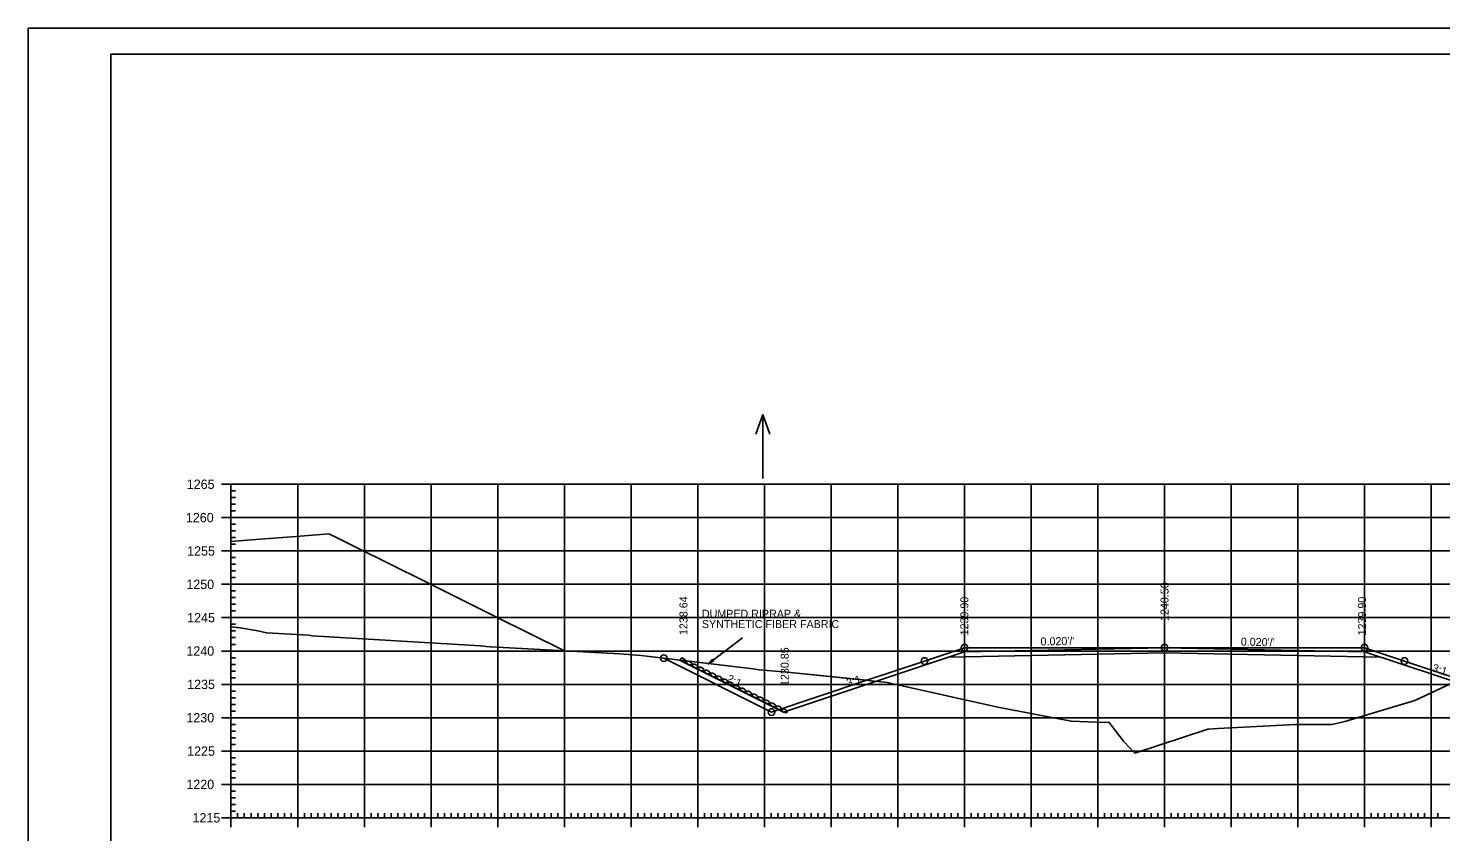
# Model space of a CAD drawing. Extents: x 1406028 to 1412453, y 321733 to 325986.
# Drawn here: x 1410609.2 to 1410821, y 322356.3 to 322476.8 of the extents above; entities that cross this region are included whole.
import ezdxf

# ---------------------------------------------------------------- set-up
doc = ezdxf.new("R2010")
doc.units = 0
for name, color, linetype in [('R_Alt Surface', 7, 'Continuous'), ('R_Axis', 7, 'Continuous'), ('R_Axis Annot', 7, 'Continuous'), ('R_Border', 7, 'Continuous'), ('R_Draft', 7, 'Continuous'), ('R_Exist Surface', 7, 'Continuous'), ('R_Fin Surface', 7, 'Continuous'), ('R_Fin Surface Annot', 7, 'Continuous'), ('R_Grid', 7, 'Continuous'), ('R_No Plot', 7, 'Continuous'), ('R_Water Annot', 7, 'Continuous')]:
    doc.layers.add(name, color=color, linetype=linetype)

msp = doc.modelspace()

# ---------------------------------------------------------------- linework, layer by layer
at = {"layer": 'R_Alt Surface'}
msp.add_lwpolyline([(1410747.2, 322382.53), (1410779.59, 322383.18), (1410811.99, 322382.53)], dxfattribs=at)
at = {"layer": 'R_Axis'}
for p, q in [((1410638.19, 322408.43), (1410640.99, 322408.43)), ((1410639.59, 322358.43), (1410639.59, 322408.43)), ((1410639.59, 322407.43), (1410640.29, 322407.43)), ((1410639.59, 322406.43), (1410640.29, 322406.43)), ((1410639.59, 322405.43), (1410640.29, 322405.43)), ((1410638.19, 322403.43), (1410640.99, 322403.43)), ((1410639.59, 322404.43), (1410640.29, 322404.43)), ((1410639.59, 322402.43), (1410640.29, 322402.43)), ((1410639.59, 322401.43), (1410640.29, 322401.43)), ((1410639.59, 322400.43), (1410640.29, 322400.43)), ((1410639.59, 322399.43), (1410640.29, 322399.43)), ((1410638.19, 322398.43), (1410640.99, 322398.43)), ((1410639.59, 322397.43), (1410640.29, 322397.43)), ((1410639.59, 322396.43), (1410640.29, 322396.43)), ((1410639.59, 322395.43), (1410640.29, 322395.43)), ((1410638.19, 322393.43), (1410640.99, 322393.43)), ((1410639.59, 322394.43), (1410640.29, 322394.43)), ((1410639.59, 322392.43), (1410640.29, 322392.43)), ((1410639.59, 322391.43), (1410640.29, 322391.43)), ((1410639.59, 322390.43), (1410640.29, 322390.43)), ((1410638.19, 322388.43), (1410640.99, 322388.43)), ((1410639.59, 322389.43), (1410640.29, 322389.43)), ((1410639.59, 322387.43), (1410640.29, 322387.43)), ((1410639.59, 322386.43), (1410640.29, 322386.43)), ((1410639.59, 322385.43), (1410640.29, 322385.43)), ((1410639.59, 322384.43), (1410640.29, 322384.43)), ((1410638.19, 322383.43), (1410640.99, 322383.43)), ((1410639.59, 322382.43), (1410640.29, 322382.43)), ((1410639.59, 322381.43), (1410640.29, 322381.43)), ((1410639.59, 322380.43), (1410640.29, 322380.43)), ((1410638.19, 322378.43), (1410640.99, 322378.43)), ((1410639.59, 322379.43), (1410640.29, 322379.43)), ((1410639.59, 322377.43), (1410640.29, 322377.43)), ((1410639.59, 322376.43), (1410640.29, 322376.43)), ((1410639.59, 322375.43), (1410640.29, 322375.43)), ((1410639.59, 322374.43), (1410640.29, 322374.43)), ((1410638.19, 322373.43), (1410640.99, 322373.43)), ((1410639.59, 322372.43), (1410640.29, 322372.43)), ((1410639.59, 322371.43), (1410640.29, 322371.43)), ((1410639.59, 322370.43), (1410640.29, 322370.43)), ((1410639.59, 322369.43), (1410640.29, 322369.43)), ((1410638.19, 322368.43), (1410640.99, 322368.43)), ((1410639.59, 322367.43), (1410640.29, 322367.43)), ((1410639.59, 322366.43), (1410640.29, 322366.43)), ((1410639.59, 322365.43), (1410640.29, 322365.43)), ((1410638.19, 322363.43), (1410640.99, 322363.43)), ((1410639.59, 322364.43), (1410640.29, 322364.43)), ((1410639.59, 322362.43), (1410640.29, 322362.43)), ((1410639.59, 322361.43), (1410640.29, 322361.43)), ((1410639.59, 322360.43), (1410640.29, 322360.43)), ((1410639.59, 322357.03), (1410639.59, 322359.83)), ((1410639.59, 322359.43), (1410640.29, 322359.43)), ((1410640.59, 322358.43), (1410640.59, 322359.13)), ((1410641.59, 322358.43), (1410641.59, 322359.13)), ((1410642.59, 322358.43), (1410642.59, 322359.13)), ((1410643.59, 322358.43), (1410643.59, 322359.13)), ((1410644.59, 322358.43), (1410644.59, 322359.13)), ((1410645.59, 322358.43), (1410645.59, 322359.13)), ((1410646.59, 322358.43), (1410646.59, 322359.13)), ((1410647.59, 322358.43), (1410647.59, 322359.13)), ((1410648.59, 322358.43), (1410648.59, 322359.13)), ((1410649.59, 322357.03), (1410649.59, 322359.83)), ((1410650.59, 322358.43), (1410650.59, 322359.13)), ((1410651.59, 322358.43), (1410651.59, 322359.13)), ((1410652.59, 322358.43), (1410652.59, 322359.13)), ((1410653.59, 322358.43), (1410653.59, 322359.13)), ((1410654.59, 322358.43), (1410654.59, 322359.13)), ((1410655.59, 322358.43), (1410655.59, 322359.13)), ((1410656.59, 322358.43), (1410656.59, 322359.13)), ((1410657.59, 322358.43), (1410657.59, 322359.13)), ((1410658.59, 322358.43), (1410658.59, 322359.13)), ((1410659.59, 322357.03), (1410659.59, 322359.83)), ((1410660.59, 322358.43), (1410660.59, 322359.13)), ((1410661.59, 322358.43), (1410661.59, 322359.13)), ((1410662.59, 322358.43), (1410662.59, 322359.13)), ((1410663.59, 322358.43), (1410663.59, 322359.13)), ((1410664.59, 322358.43), (1410664.59, 322359.13)), ((1410665.59, 322358.43), (1410665.59, 322359.13)), ((1410666.59, 322358.43), (1410666.59, 322359.13)), ((1410667.59, 322358.43), (1410667.59, 322359.13)), ((1410668.59, 322358.43), (1410668.59, 322359.13)), ((1410669.59, 322357.03), (1410669.59, 322359.83)), ((1410670.59, 322358.43), (1410670.59, 322359.13)), ((1410671.59, 322358.43), (1410671.59, 322359.13)), ((1410672.59, 322358.43), (1410672.59, 322359.13)), ((1410673.59, 322358.43), (1410673.59, 322359.13)), ((1410674.59, 322358.43), (1410674.59, 322359.13)), ((1410675.59, 322358.43), (1410675.59, 322359.13)), ((1410676.59, 322358.43), (1410676.59, 322359.13)), ((1410677.59, 322358.43), (1410677.59, 322359.13)), ((1410678.59, 322358.43), (1410678.59, 322359.13)), ((1410679.59, 322357.03), (1410679.59, 322359.83)), ((1410680.59, 322358.43), (1410680.59, 322359.13)), ((1410681.59, 322358.43), (1410681.59, 322359.13)), ((1410682.59, 322358.43), (1410682.59, 322359.13)), ((1410683.59, 322358.43), (1410683.59, 322359.13)), ((1410684.59, 322358.43), (1410684.59, 322359.13)), ((1410685.59, 322358.43), (1410685.59, 322359.13)), ((1410686.59, 322358.43), (1410686.59, 322359.13)), ((1410687.59, 322358.43), (1410687.59, 322359.13)), ((1410688.59, 322358.43), (1410688.59, 322359.13)), ((1410689.59, 322357.03), (1410689.59, 322359.83)), ((1410690.59, 322358.43), (1410690.59, 322359.13)), ((1410691.59, 322358.43), (1410691.59, 322359.13)), ((1410692.59, 322358.43), (1410692.59, 322359.13)), ((1410693.59, 322358.43), (1410693.59, 322359.13)), ((1410694.59, 322358.43), (1410694.59, 322359.13)), ((1410695.59, 322358.43), (1410695.59, 322359.13)), ((1410696.59, 322358.43), (1410696.59, 322359.13)), ((1410697.59, 322358.43), (1410697.59, 322359.13)), ((1410698.59, 322358.43), (1410698.59, 322359.13)), ((1410699.59, 322357.03), (1410699.59, 322359.83)), ((1410700.59, 322358.43), (1410700.59, 322359.13)), ((1410701.59, 322358.43), (1410701.59, 322359.13)), ((1410702.59, 322358.43), (1410702.59, 322359.13)), ((1410703.59, 322358.43), (1410703.59, 322359.13)), ((1410704.59, 322358.43), (1410704.59, 322359.13)), ((1410705.59, 322358.43), (1410705.59, 322359.13)), ((1410706.59, 322358.43), (1410706.59, 322359.13)), ((1410707.59, 322358.43), (1410707.59, 322359.13)), ((1410708.59, 322358.43), (1410708.59, 322359.13)), ((1410709.59, 322357.03), (1410709.59, 322359.83)), ((1410710.59, 322358.43), (1410710.59, 322359.13)), ((1410711.59, 322358.43), (1410711.59, 322359.13)), ((1410712.59, 322358.43), (1410712.59, 322359.13)), ((1410713.59, 322358.43), (1410713.59, 322359.13)), ((1410714.59, 322358.43), (1410714.59, 322359.13)), ((1410715.59, 322358.43), (1410715.59, 322359.13)), ((1410716.59, 322358.43), (1410716.59, 322359.13)), ((1410717.59, 322358.43), (1410717.59, 322359.13)), ((1410718.59, 322358.43), (1410718.59, 322359.13)), ((1410719.59, 322357.03), (1410719.59, 322359.83)), ((1410720.59, 322358.43), (1410720.59, 322359.13)), ((1410721.59, 322358.43), (1410721.59, 322359.13)), ((1410722.59, 322358.43), (1410722.59, 322359.13)), ((1410723.59, 322358.43), (1410723.59, 322359.13)), ((1410724.59, 322358.43), (1410724.59, 322359.13)), ((1410725.59, 322358.43), (1410725.59, 322359.13)), ((1410726.59, 322358.43), (1410726.59, 322359.13)), ((1410727.59, 322358.43), (1410727.59, 322359.13)), ((1410728.59, 322358.43), (1410728.59, 322359.13)), ((1410729.59, 322357.03), (1410729.59, 322359.83)), ((1410730.59, 322358.43), (1410730.59, 322359.13)), ((1410731.59, 322358.43), (1410731.59, 322359.13)), ((1410732.59, 322358.43), (1410732.59, 322359.13)), ((1410733.59, 322358.43), (1410733.59, 322359.13)), ((1410734.59, 322358.43), (1410734.59, 322359.13)), ((1410735.59, 322358.43), (1410735.59, 322359.13)), ((1410736.59, 322358.43), (1410736.59, 322359.13)), ((1410737.59, 322358.43), (1410737.59, 322359.13)), ((1410738.59, 322358.43), (1410738.59, 322359.13)), ((1410739.59, 322357.03), (1410739.59, 322359.83)), ((1410740.59, 322358.43), (1410740.59, 322359.13)), ((1410741.59, 322358.43), (1410741.59, 322359.13)), ((1410742.59, 322358.43), (1410742.59, 322359.13)), ((1410743.59, 322358.43), (1410743.59, 322359.13)), ((1410744.59, 322358.43), (1410744.59, 322359.13)), ((1410745.59, 322358.43), (1410745.59, 322359.13)), ((1410746.59, 322358.43), (1410746.59, 322359.13)), ((1410747.59, 322358.43), (1410747.59, 322359.13)), ((1410748.59, 322358.43), (1410748.59, 322359.13)), ((1410749.59, 322357.03), (1410749.59, 322359.83)), ((1410750.59, 322358.43), (1410750.59, 322359.13)), ((1410751.59, 322358.43), (1410751.59, 322359.13)), ((1410752.59, 322358.43), (1410752.59, 322359.13)), ((1410753.59, 322358.43), (1410753.59, 322359.13)), ((1410754.59, 322358.43), (1410754.59, 322359.13)), ((1410755.59, 322358.43), (1410755.59, 322359.13)), ((1410756.59, 322358.43), (1410756.59, 322359.13)), ((1410757.59, 322358.43), (1410757.59, 322359.13)), ((1410758.59, 322358.43), (1410758.59, 322359.13)), ((1410759.59, 322357.03), (1410759.59, 322359.83)), ((1410760.59, 322358.43), (1410760.59, 322359.13)), ((1410761.59, 322358.43), (1410761.59, 322359.13)), ((1410762.59, 322358.43), (1410762.59, 322359.13)), ((1410763.59, 322358.43), (1410763.59, 322359.13)), ((1410764.59, 322358.43), (1410764.59, 322359.13)), ((1410765.59, 322358.43), (1410765.59, 322359.13)), ((1410766.59, 322358.43), (1410766.59, 322359.13)), ((1410767.59, 322358.43), (1410767.59, 322359.13)), ((1410768.59, 322358.43), (1410768.59, 322359.13)), ((1410769.59, 322357.03), (1410769.59, 322359.83)), ((1410770.59, 322358.43), (1410770.59, 322359.13)), ((1410771.59, 322358.43), (1410771.59, 322359.13)), ((1410772.59, 322358.43), (1410772.59, 322359.13)), ((1410773.59, 322358.43), (1410773.59, 322359.13)), ((1410774.59, 322358.43), (1410774.59, 322359.13)), ((1410775.59, 322358.43), (1410775.59, 322359.13)), ((1410776.59, 322358.43), (1410776.59, 322359.13)), ((1410777.59, 322358.43), (1410777.59, 322359.13)), ((1410778.59, 322358.43), (1410778.59, 322359.13)), ((1410779.59, 322357.03), (1410779.59, 322359.83)), ((1410780.59, 322358.43), (1410780.59, 322359.13)), ((1410781.59, 322358.43), (1410781.59, 322359.13)), ((1410782.59, 322358.43), (1410782.59, 322359.13)), ((1410783.59, 322358.43), (1410783.59, 322359.13)), ((1410784.59, 322358.43), (1410784.59, 322359.13)), ((1410785.59, 322358.43), (1410785.59, 322359.13)), ((1410786.59, 322358.43), (1410786.59, 322359.13)), ((1410787.59, 322358.43), (1410787.59, 322359.13)), ((1410788.59, 322358.43), (1410788.59, 322359.13)), ((1410789.59, 322357.03), (1410789.59, 322359.83)), ((1410790.59, 322358.43), (1410790.59, 322359.13)), ((1410791.59, 322358.43), (1410791.59, 322359.13)), ((1410792.59, 322358.43), (1410792.59, 322359.13)), ((1410793.59, 322358.43), (1410793.59, 322359.13)), ((1410794.59, 322358.43), (1410794.59, 322359.13)), ((1410795.59, 322358.43), (1410795.59, 322359.13)), ((1410796.59, 322358.43), (1410796.59, 322359.13)), ((1410797.59, 322358.43), (1410797.59, 322359.13)), ((1410798.59, 322358.43), (1410798.59, 322359.13)), ((1410799.59, 322357.03), (1410799.59, 322359.83)), ((1410800.59, 322358.43), (1410800.59, 322359.13)), ((1410801.59, 322358.43), (1410801.59, 322359.13)), ((1410802.59, 322358.43), (1410802.59, 322359.13)), ((1410803.59, 322358.43), (1410803.59, 322359.13)), ((1410804.59, 322358.43), (1410804.59, 322359.13)), ((1410805.59, 322358.43), (1410805.59, 322359.13)), ((1410806.59, 322358.43), (1410806.59, 322359.13)), ((1410807.59, 322358.43), (1410807.59, 322359.13)), ((1410808.59, 322358.43), (1410808.59, 322359.13)), ((1410809.59, 322357.03), (1410809.59, 322359.83)), ((1410810.59, 322358.43), (1410810.59, 322359.13)), ((1410811.59, 322358.43), (1410811.59, 322359.13)), ((1410812.59, 322358.43), (1410812.59, 322359.13)), ((1410813.59, 322358.43), (1410813.59, 322359.13)), ((1410814.59, 322358.43), (1410814.59, 322359.13)), ((1410815.59, 322358.43), (1410815.59, 322359.13)), ((1410816.59, 322358.43), (1410816.59, 322359.13)), ((1410817.59, 322358.43), (1410817.59, 322359.13)), ((1410818.59, 322358.43), (1410818.59, 322359.13)), ((1410819.59, 322357.03), (1410819.59, 322359.83)), ((1410820.59, 322358.43), (1410820.59, 322359.13)), ((1410638.19, 322358.43), (1410640.99, 322358.43)), ((1410639.59, 322358.43), (1410919.59, 322358.43))]:
    msp.add_line(p, q, dxfattribs=at)
at = {"layer": 'R_Border'}
for p, q in [((1410621.59, 322472.89), (1410937.77, 322472.89)), ((1410621.59, 322267.43), (1410621.59, 322472.89)), ((1410774.11, 322472.63), (1410774.11, 322472.63)), ((1410774.11, 322472.63), (1410774.11, 322472.63))]:
    msp.add_line(p, q, dxfattribs=at)
at = {"layer": 'R_Draft'}
for p, q in [((1410716.31, 322385.39), (1410711.08, 322381.47)), ((1410711.79, 322382.19), (1410711.08, 322381.47)), ((1410711.8, 322382.17), (1410711.21, 322381.57)), ((1410711.95, 322381.97), (1410711.21, 322381.57)), ((1410711.82, 322382.14), (1410711.35, 322381.67)), ((1410711.94, 322381.99), (1410711.35, 322381.67)), ((1410711.83, 322382.12), (1410711.48, 322381.77)), ((1410711.92, 322382.01), (1410711.48, 322381.77)), ((1410711.85, 322382.1), (1410711.62, 322381.87)), ((1410711.91, 322382.03), (1410711.62, 322381.87)), ((1410711.86, 322382.08), (1410711.75, 322381.97)), ((1410711.89, 322382.05), (1410711.75, 322381.97)), ((1410711.79, 322382.19), (1410711.97, 322381.95)), ((1410711.97, 322381.95), (1410711.08, 322381.47))]:
    msp.add_line(p, q, dxfattribs=at)
for centre in [(1410707.42, 322382.07), (1410708.31, 322381.62), (1410709.21, 322381.17), (1410710.1, 322380.73), (1410711, 322380.28), (1410711.89, 322379.83), (1410712.78, 322379.39), (1410713.68, 322378.94), (1410714.57, 322378.49), (1410715.47, 322378.04), (1410716.36, 322377.6), (1410717.26, 322377.15), (1410718.15, 322376.7), (1410719.05, 322376.26), (1410719.94, 322375.81), (1410720.83, 322375.36), (1410721.73, 322374.91), (1410722.62, 322374.47)]:
    msp.add_ellipse(centre, major_axis=(0.389, -0.201), ratio=0.517889, dxfattribs=at)
at = {"layer": 'R_Exist Surface'}
msp.add_lwpolyline([(1410639.59, 322387.04), (1410640.97, 322386.89), (1410643.63, 322386.43), (1410644.91, 322386.15), (1410651.23, 322385.78), (1410651.78, 322385.7), (1410676.99, 322384.22), (1410677.87, 322384.13), (1410678.46, 322384.08), (1410679.51, 322384.02), (1410697.89, 322382.99), (1410701.09, 322382.75), (1410717.91, 322380.75), (1410718.8, 322380.63), (1410722.99, 322380.25), (1410735.65, 322378.97), (1410738.02, 322378.69), (1410754.61, 322375.03), (1410765.59, 322372.93), (1410770.6, 322372.71), (1410771.24, 322372.78), (1410773.43, 322369.89), (1410775.12, 322368.14), (1410785.79, 322371.59), (1410786.07, 322371.7), (1410786.09, 322371.7), (1410786.18, 322371.72), (1410787.58, 322371.79), (1410799.23, 322372.41), (1410804.73, 322372.39), (1410806.61, 322372.84), (1410817.15, 322376.03), (1410824.38, 322379.42)], dxfattribs=at)
at = {"layer": 'R_Fin Surface'}
for p, q in [((1410722.44, 322374.28), (1410706.87, 322382.06)), ((1410749.59, 322383.33), (1410722.44, 322374.28)), ((1410809.59, 322383.33), (1410830.78, 322376.26))]:
    msp.add_line(p, q, dxfattribs=at)
for points in [[(1410639.59, 322399.84), (1410642.68, 322400.09), (1410649.34, 322400.62), (1410654.24, 322401.01), (1410655.51, 322400.38), (1410658.73, 322398.78), (1410662.74, 322396.79), (1410669.41, 322393.48), (1410679.3, 322388.57), (1410689.6, 322383.46)], [(1410749.59, 322383.33), (1410779.59, 322383.93), (1410809.59, 322383.33)]]:
    msp.add_lwpolyline(points, dxfattribs=at)
at = {"layer": 'R_Grid'}
for p, q in [((1410639.59, 322408.43), (1410919.59, 322408.43)), ((1410639.59, 322358.43), (1410639.59, 322408.43)), ((1410649.59, 322358.43), (1410649.59, 322408.43)), ((1410659.59, 322358.43), (1410659.59, 322408.43)), ((1410669.59, 322358.43), (1410669.59, 322408.43)), ((1410679.59, 322358.43), (1410679.59, 322408.43)), ((1410689.59, 322358.43), (1410689.59, 322408.43)), ((1410699.59, 322358.43), (1410699.59, 322408.43)), ((1410709.59, 322358.43), (1410709.59, 322408.43)), ((1410719.59, 322358.43), (1410719.59, 322408.43)), ((1410729.59, 322358.43), (1410729.59, 322408.43)), ((1410739.59, 322358.43), (1410739.59, 322408.43)), ((1410749.59, 322358.43), (1410749.59, 322408.43)), ((1410759.59, 322358.43), (1410759.59, 322408.43)), ((1410769.59, 322358.43), (1410769.59, 322408.43)), ((1410779.59, 322358.43), (1410779.59, 322408.43)), ((1410789.59, 322358.43), (1410789.59, 322408.43)), ((1410799.59, 322358.43), (1410799.59, 322408.43)), ((1410809.59, 322358.43), (1410809.59, 322408.43)), ((1410819.59, 322358.43), (1410819.59, 322408.43)), ((1410639.59, 322403.43), (1410919.59, 322403.43)), ((1410639.59, 322398.43), (1410919.59, 322398.43)), ((1410639.59, 322393.43), (1410919.59, 322393.43)), ((1410639.59, 322388.43), (1410919.59, 322388.43)), ((1410639.59, 322383.43), (1410919.59, 322383.43)), ((1410639.59, 322378.43), (1410919.59, 322378.43)), ((1410639.59, 322373.43), (1410919.59, 322373.43)), ((1410639.59, 322368.43), (1410919.59, 322368.43)), ((1410639.59, 322363.43), (1410919.59, 322363.43)), ((1410639.59, 322358.43), (1410919.59, 322358.43))]:
    msp.add_line(p, q, dxfattribs=at)
at = {"layer": 'R_No Plot'}
msp.add_line((1410609.19, 322476.78), (1410942.52, 322476.78), dxfattribs=at)
for points in [[(1410609.18, 322476.78), (1410942.52, 322476.78), (1410942.52, 322263.44), (1410609.18, 322263.44)], [(1410855.51, 322472.89), (1410875.13, 322472.89), (1410875.13, 322463.01), (1410891.24, 322463.01), (1410914.44, 322463.01), (1410914.44, 322438.67), (1410937.77, 322438.67), (1410937.77, 322267.43), (1410621.59, 322267.43), (1410621.59, 322472.89)], [(1410704.51, 322382.35), (1410717.91, 322380.75), (1410718.8, 322380.63), (1410722.99, 322380.25), (1410734.93, 322379.04), (1410720.64, 322374.28)], [(1410734.93, 322379.04), (1410735.65, 322378.97), (1410738.02, 322378.69), (1410754.61, 322375.03), (1410765.59, 322372.93), (1410770.6, 322372.71), (1410771.24, 322372.78), (1410773.43, 322369.89), (1410775.12, 322368.14), (1410785.79, 322371.59), (1410786.07, 322371.7), (1410786.09, 322371.7), (1410786.18, 322371.72), (1410787.58, 322371.79), (1410799.23, 322372.41), (1410804.73, 322372.39), (1410806.61, 322372.84), (1410817.15, 322376.03), (1410823.86, 322379.17), (1410815.59, 322381.93), (1410809.59, 322383.93), (1410779.59, 322383.93), (1410749.59, 322383.93), (1410743.59, 322381.93)]]:
    msp.add_lwpolyline(points, close=True, dxfattribs=at)
for centre in [(1410749.59, 322383.93), (1410749.59, 322383.93), (1410779.59, 322383.93), (1410809.59, 322383.93), (1410809.59, 322383.93), (1410704.51, 322382.35), (1410743.59, 322381.93), (1410815.59, 322381.93), (1410720.64, 322374.28), (1410720.64, 322374.28)]:
    msp.add_circle(centre, 0.5, dxfattribs=at)
at = {"layer": 'R_Water Annot'}
for p, q in [((1410719.35, 322418.86), (1410718.28, 322415.93)), ((1410719.35, 322409.28), (1410719.35, 322418.86)), ((1410719.35, 322418.86), (1410720.42, 322415.93))]:
    msp.add_line(p, q, dxfattribs=at)

# ---------------------------------------------------------------- texts
at = {"layer": 'R_Axis Annot'}
for s, p in [('1265', (1410632.96, 322407.73)), ('1260', (1410632.83, 322402.73)), ('1255', (1410633.02, 322397.73)), ('1250', (1410632.9, 322392.73)), ('1245', (1410633.02, 322387.73)), ('1240', (1410632.9, 322382.73)), ('1235', (1410633.02, 322377.73)), ('1230', (1410632.9, 322372.73)), ('1225', (1410633.02, 322367.73)), ('1220', (1410632.9, 322362.73)), ('1215', (1410633.82, 322357.73))]:
    msp.add_text(s, height=1.4, dxfattribs=at).set_placement(p)
at = {"layer": 'R_Draft'}
for s, p in [('DUMPED RIPRAP &', (1410710.21, 322388.41)), ('SYNTHETIC FIBER FABRIC', (1410710.21, 322386.87))]:
    msp.add_text(s, height=1.2, dxfattribs=at).set_placement(p)
at = {"layer": 'R_Fin Surface Annot'}
for s, rotation, p in [('1240.50', 90, (1410780.19, 322387.93)), ('1238.64', 90, (1410708.05, 322385.82)), ('1239.90', 90, (1410750.17, 322385.77)), ('1239.90', 90, (1410809.81, 322385.77)), ("0.020'/'", 1.1458, (1410761.01, 322384.25)), ("0.020'/'", 358.8542, (1410791.02, 322384.24)), ('1230.85', 90, (1410723.23, 322378.18)), ('2:1', 333.4349, (1410713.81, 322378.92)), ('3:1', 341.5651, (1410819.63, 322380.41)), ('3:1', 18.4349, (1410732.12, 322378.02))]:
    msp.add_text(s, height=1.2, rotation=rotation, dxfattribs=at).set_placement(p)

doc.saveas('drawing.dxf')
